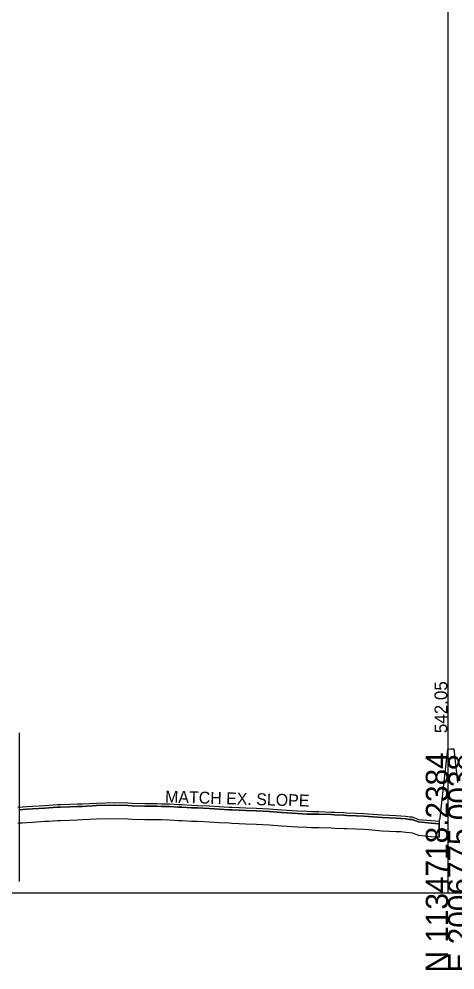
# Model space of a CAD drawing. Extents: x -201 to 2007062, y -213 to 1139737.
# Drawn here: x 1196 to 1250.9, y 1990.3 to 2109.9 of the extents above; entities that cross this region are included whole.
import ezdxf

# ---------------------------------------------------------------- set-up
doc = ezdxf.new("R2010")
doc.units = 0
for name, color, linetype in [('RD_GPK_XS_Cell', 7, 'Continuous'), ('RD_XS_ExGround', 7, 'Continuous'), ('RD_XS_ExPaveRet', 7, 'Continuous'), ('RD_XS_PaveOvlay', 7, 'Continuous'), ('RD_XS_SideStreet', 7, 'Continuous'), ('RD_XS_TX_Elev_EX', 7, 'Continuous'), ('RD_XS_TX_Slope', 7, 'Continuous')]:
    doc.layers.add(name, color=color, linetype=linetype)

msp = doc.modelspace()

# ---------------------------------------------------------------- linework, layer by layer
at = {"layer": 'RD_GPK_XS_Cell'}
for p, q in [((1250, 2000), (1250, 2226.79)), ((1000, 2000), (1250, 2000)), ((1250, 2000), (1500, 2000))]:
    msp.add_line(p, q, dxfattribs=at)
at = {"layer": 'RD_XS_ExGround'}
msp.add_lwpolyline([(1195.84, 2010.79), (1196.97, 2010.88), (1197.69, 2010.91), (1199.26, 2011.02), (1199.74, 2011.04), (1200.83, 2011.11), (1201.21, 2011.13), (1202.39, 2011.17), (1203.33, 2011.2), (1203.96, 2011.23), (1205.74, 2011.31), (1208.04, 2011.37), (1209.7, 2011.32), (1210.23, 2011.3), (1211.82, 2011.26), (1213.36, 2011.24), (1213.94, 2011.22), (1214.93, 2011.19), (1216.06, 2011.13), (1216.5, 2011.11), (1217.73, 2011.05), (1218.45, 2011.02), (1219.95, 2010.95), (1220.56, 2010.91), (1221.2, 2010.87), (1222.43, 2010.8), (1222.77, 2010.79), (1223.73, 2010.74), (1224.55, 2010.7), (1225.9, 2010.65), (1226.67, 2010.62), (1227.47, 2010.57), (1229.03, 2010.46), (1229.73, 2010.42), (1231.03, 2010.33), (1232.27, 2010.27), (1232.81, 2010.25), (1233.74, 2010.25), (1235.3, 2010.18), (1235.72, 2010.16), (1236.87, 2010.11), (1237.28, 2010.09), (1238.44, 2010.05), (1239.4, 2010.01), (1240, 2009.97), (1241.72, 2009.81), (1243.48, 2009.73), (1244.05, 2009.71), (1244.7, 2009.65), (1245.17, 2009.59), (1245.48, 2009.56), (1246.27, 2009.26), (1247.87, 2009.1), (1248.88, 2009.03), (1248.99, 2009.42), (1249.51, 2014.04), (1249.97, 2018.1), (1250.32, 2018.11), (1250.74, 2018.12), (1251.17, 2013.89)], dxfattribs=at)
at = {"layer": 'RD_XS_ExPaveRet'}
for p, q in [((1196, 2010.47), (1196, 2008.8)), ((1195.84, 2008.79), (1196.97, 2008.88)), ((1196, 2008.8), (1196.97, 2008.88)), ((1196.97, 2008.88), (1197.69, 2008.91)), ((1196.97, 2008.88), (1197.69, 2008.91)), ((1197.69, 2008.91), (1199.26, 2009.02)), ((1197.69, 2008.91), (1199.26, 2009.02)), ((1199.26, 2009.02), (1199.74, 2009.04)), ((1199.26, 2009.02), (1199.74, 2009.04)), ((1199.74, 2009.04), (1200.83, 2009.11)), ((1199.74, 2009.04), (1200.83, 2009.11)), ((1200.83, 2009.11), (1201.21, 2009.13)), ((1200.83, 2009.11), (1201.21, 2009.13)), ((1201.21, 2009.13), (1202.39, 2009.17)), ((1201.21, 2009.13), (1202.39, 2009.17)), ((1202.39, 2009.17), (1203.33, 2009.2)), ((1202.39, 2009.17), (1203.33, 2009.2)), ((1203.33, 2009.2), (1203.96, 2009.23)), ((1203.33, 2009.2), (1203.96, 2009.23)), ((1203.96, 2009.23), (1205.74, 2009.31)), ((1203.96, 2009.23), (1205.74, 2009.31)), ((1205.74, 2009.31), (1208.04, 2009.37)), ((1205.74, 2009.31), (1208.04, 2009.37)), ((1208.04, 2009.37), (1209.7, 2009.32)), ((1208.04, 2009.37), (1209.7, 2009.32)), ((1209.7, 2009.32), (1210.23, 2009.3)), ((1209.7, 2009.32), (1210.23, 2009.3)), ((1210.23, 2009.3), (1211.82, 2009.26)), ((1210.23, 2009.3), (1211.82, 2009.26)), ((1211.82, 2009.26), (1213.36, 2009.24)), ((1211.82, 2009.26), (1213.36, 2009.24)), ((1213.36, 2009.24), (1213.94, 2009.22)), ((1213.36, 2009.24), (1213.94, 2009.22)), ((1213.94, 2009.22), (1214.93, 2009.19)), ((1213.94, 2009.22), (1214.93, 2009.19)), ((1214.93, 2009.19), (1216.06, 2009.13)), ((1214.93, 2009.19), (1216.06, 2009.13)), ((1216.06, 2009.13), (1216.5, 2009.11)), ((1216.06, 2009.13), (1216.5, 2009.11)), ((1216.5, 2009.11), (1217.73, 2009.05)), ((1216.5, 2009.11), (1217.73, 2009.05)), ((1217.73, 2009.05), (1218.45, 2009.02)), ((1217.73, 2009.05), (1218.45, 2009.02)), ((1218.45, 2009.02), (1219.95, 2008.95)), ((1218.45, 2009.02), (1219.95, 2008.95)), ((1219.95, 2008.95), (1220.56, 2008.91)), ((1219.95, 2008.95), (1220.56, 2008.91)), ((1220.56, 2008.91), (1221.2, 2008.87)), ((1220.56, 2008.91), (1221.2, 2008.87)), ((1221.2, 2008.87), (1222.43, 2008.8)), ((1221.2, 2008.87), (1222.43, 2008.8)), ((1222.43, 2008.8), (1222.77, 2008.79)), ((1222.43, 2008.8), (1222.77, 2008.79)), ((1222.77, 2008.79), (1223.73, 2008.74)), ((1222.77, 2008.79), (1223.73, 2008.74)), ((1248.88, 2009.03), (1248.88, 2007.03)), ((1223.73, 2008.74), (1224.55, 2008.7)), ((1223.73, 2008.74), (1224.55, 2008.7)), ((1224.55, 2008.7), (1225.9, 2008.65)), ((1224.55, 2008.7), (1225.9, 2008.65)), ((1225.9, 2008.65), (1226.67, 2008.62)), ((1225.9, 2008.65), (1226.67, 2008.62)), ((1226.67, 2008.62), (1227.47, 2008.57)), ((1226.67, 2008.62), (1227.47, 2008.57)), ((1227.47, 2008.57), (1229.03, 2008.46)), ((1227.47, 2008.57), (1229.03, 2008.46)), ((1229.03, 2008.46), (1229.73, 2008.42)), ((1229.03, 2008.46), (1229.73, 2008.42)), ((1229.73, 2008.42), (1231.03, 2008.33)), ((1229.73, 2008.42), (1231.03, 2008.33)), ((1231.03, 2008.33), (1232.27, 2008.27)), ((1231.03, 2008.33), (1232.27, 2008.27)), ((1232.27, 2008.27), (1232.81, 2008.25)), ((1232.27, 2008.27), (1232.81, 2008.25)), ((1232.81, 2008.25), (1233.74, 2008.25)), ((1232.81, 2008.25), (1233.74, 2008.25)), ((1233.74, 2008.25), (1235.3, 2008.18)), ((1233.74, 2008.25), (1235.3, 2008.18)), ((1235.3, 2008.18), (1235.72, 2008.16)), ((1235.3, 2008.18), (1235.72, 2008.16)), ((1235.72, 2008.16), (1236.87, 2008.11)), ((1235.72, 2008.16), (1236.87, 2008.11)), ((1236.87, 2008.11), (1237.28, 2008.09)), ((1236.87, 2008.11), (1237.28, 2008.09)), ((1237.28, 2008.09), (1238.44, 2008.05)), ((1237.28, 2008.09), (1238.44, 2008.05)), ((1238.44, 2008.05), (1239.4, 2008.01)), ((1238.44, 2008.05), (1239.4, 2008.01)), ((1239.4, 2008.01), (1240, 2007.97)), ((1239.4, 2008.01), (1240, 2007.97)), ((1240, 2007.97), (1241.72, 2007.81)), ((1240, 2007.97), (1241.72, 2007.81)), ((1241.72, 2007.81), (1243.48, 2007.73)), ((1241.72, 2007.81), (1243.48, 2007.73)), ((1243.48, 2007.73), (1244.05, 2007.71)), ((1243.48, 2007.73), (1244.05, 2007.71)), ((1244.05, 2007.71), (1244.7, 2007.65)), ((1244.05, 2007.71), (1244.7, 2007.65)), ((1244.7, 2007.65), (1245.17, 2007.59)), ((1244.7, 2007.65), (1245.17, 2007.59)), ((1245.17, 2007.59), (1245.48, 2007.56)), ((1245.17, 2007.59), (1245.48, 2007.56)), ((1245.48, 2007.56), (1246.27, 2007.26)), ((1245.48, 2007.56), (1246.27, 2007.26)), ((1248.88, 2007.03), (1248.88, 2008.7)), ((1246.27, 2007.26), (1247.87, 2007.1)), ((1246.27, 2007.26), (1247.87, 2007.1)), ((1247.87, 2007.1), (1248.88, 2007.03)), ((1247.87, 2007.1), (1248.88, 2007.03))]:
    msp.add_line(p, q, dxfattribs=at)
for points in [[(1248.88, 2008.7), (1247.87, 2008.76), (1246.27, 2008.93), (1245.48, 2009.23), (1245.17, 2009.26), (1244.7, 2009.32), (1244.05, 2009.38), (1243.48, 2009.4), (1241.72, 2009.48), (1240, 2009.63), (1239.4, 2009.67), (1238.44, 2009.72), (1237.28, 2009.76), (1236.87, 2009.78), (1235.72, 2009.83), (1235.3, 2009.85), (1233.74, 2009.91), (1232.81, 2009.92), (1232.27, 2009.93), (1231.03, 2010), (1229.73, 2010.08), (1229.03, 2010.13), (1227.47, 2010.23), (1226.67, 2010.29), (1225.9, 2010.32), (1224.55, 2010.37), (1223.73, 2010.41), (1222.77, 2010.46), (1222.43, 2010.47), (1221.2, 2010.54), (1220.56, 2010.57), (1219.95, 2010.62), (1218.45, 2010.69), (1217.73, 2010.72), (1216.5, 2010.78), (1216.06, 2010.8), (1214.93, 2010.86), (1213.94, 2010.89), (1213.36, 2010.91), (1211.82, 2010.93), (1210.23, 2010.97), (1209.7, 2010.99), (1208.04, 2011.03), (1205.74, 2010.98), (1203.96, 2010.89), (1203.33, 2010.87), (1202.39, 2010.84), (1201.21, 2010.79), (1200.83, 2010.77), (1199.74, 2010.71), (1199.26, 2010.68), (1197.69, 2010.58), (1196.97, 2010.55), (1196, 2010.47)], [(1248.88, 2008.7), (1248.88, 2008.7)]]:
    msp.add_lwpolyline(points, dxfattribs=at)
at = {"layer": 'RD_XS_PaveOvlay'}
msp.add_line((1196, 2010.8), (1196, 2010.47), dxfattribs=at)
for points in [[(1196, 2010.8), (1196.97, 2010.88), (1197.69, 2010.91), (1199.26, 2011.02), (1199.74, 2011.04), (1200.83, 2011.11), (1201.21, 2011.13), (1202.39, 2011.17), (1203.33, 2011.2), (1203.96, 2011.23), (1205.74, 2011.31), (1208.04, 2011.37), (1209.7, 2011.32), (1210.23, 2011.3), (1211.82, 2011.26), (1213.36, 2011.24), (1213.94, 2011.22), (1214.93, 2011.19), (1216.06, 2011.13), (1216.5, 2011.11), (1217.73, 2011.05), (1218.45, 2011.02), (1219.95, 2010.95), (1220.56, 2010.91), (1221.2, 2010.87), (1222.43, 2010.8), (1222.77, 2010.79), (1223.73, 2010.74), (1224.55, 2010.7), (1225.9, 2010.65), (1226.67, 2010.62), (1227.47, 2010.57), (1229.03, 2010.46), (1229.73, 2010.42), (1231.03, 2010.33), (1232.27, 2010.27), (1232.81, 2010.25), (1233.74, 2010.25), (1235.3, 2010.18), (1235.72, 2010.16), (1236.87, 2010.11), (1237.28, 2010.09), (1238.44, 2010.05), (1239.4, 2010.01), (1240, 2009.97), (1241.72, 2009.81), (1243.48, 2009.73), (1244.05, 2009.71), (1244.7, 2009.65), (1245.17, 2009.59), (1245.48, 2009.56), (1246.27, 2009.26), (1247.87, 2009.1), (1248.88, 2009.03)], [(1196, 2010.47), (1196.97, 2010.55), (1197.69, 2010.58), (1199.26, 2010.68), (1199.74, 2010.71), (1200.83, 2010.77), (1201.21, 2010.79), (1202.39, 2010.84), (1203.33, 2010.87), (1203.96, 2010.89), (1205.74, 2010.98), (1208.04, 2011.03), (1209.7, 2010.99), (1210.23, 2010.97), (1211.82, 2010.93), (1213.36, 2010.91), (1213.94, 2010.89), (1214.93, 2010.86), (1216.06, 2010.8), (1216.5, 2010.78), (1217.73, 2010.72), (1218.45, 2010.69), (1219.95, 2010.62), (1220.56, 2010.57), (1221.2, 2010.54), (1222.43, 2010.47), (1222.77, 2010.46), (1223.73, 2010.41), (1224.55, 2010.37), (1225.9, 2010.32), (1226.67, 2010.29), (1227.47, 2010.23), (1229.03, 2010.13), (1229.73, 2010.08), (1231.03, 2010), (1232.27, 2009.93), (1232.81, 2009.92), (1233.74, 2009.91), (1235.3, 2009.85), (1235.72, 2009.83), (1236.87, 2009.78), (1237.28, 2009.76), (1238.44, 2009.72), (1239.4, 2009.67), (1240, 2009.63), (1241.72, 2009.48), (1243.48, 2009.4), (1244.05, 2009.38), (1244.7, 2009.32), (1245.17, 2009.26), (1245.48, 2009.23), (1246.27, 2008.93), (1247.87, 2008.76), (1248.88, 2008.7)]]:
    msp.add_lwpolyline(points, dxfattribs=at)
at = {"layer": 'RD_XS_SideStreet'}
msp.add_line((1196, 2020.13), (1196, 2001.45), dxfattribs=at)

# ---------------------------------------------------------------- texts
at = {"layer": 'RD_GPK_XS_Cell'}
for s, p in [('N 1134718.2384', (1250, 1990)), ('E 2006775.0038', (1252.8, 1990))]:
    msp.add_text(s, height=2.8, rotation=90, dxfattribs=at).set_placement(p)
at = {"layer": 'RD_XS_TX_Elev_EX'}
msp.add_text('542.05', height=1.6, rotation=90, dxfattribs=at).set_placement((1249.9, 2020.1))
at = {"layer": 'RD_XS_TX_Slope'}
msp.add_text('MATCH EX. SLOPE', height=1.5, rotation=358.3671, dxfattribs=at).set_placement((1214.37, 2011.38))

doc.saveas('drawing.dxf')
